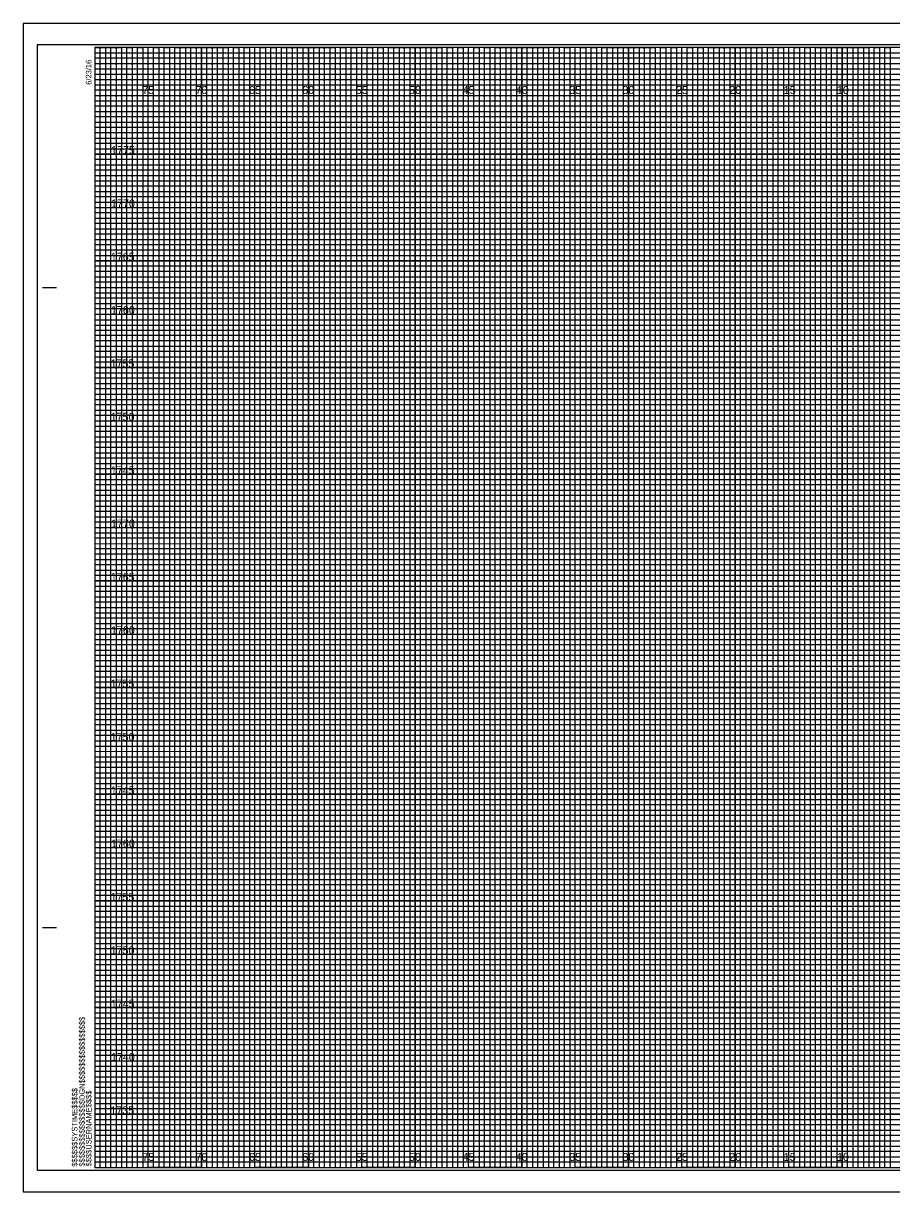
# Model space of a CAD drawing. Extents: x 224 to 392, y 1 to 440.
# Drawn here: x 223.6 to 304.9, y 1 to 110.5 of the extents above; entities that cross this region are included whole.
import ezdxf

# ---------------------------------------------------------------- set-up
doc = ezdxf.new("R2010")
doc.units = 0
for name, color, linetype in [('Prop Grid Mask', 7, 'Continuous'), ('Prop XS Elevation Labels', 7, 'Continuous'), ('Sheet Cross Section CELL', 7, 'Continuous'), ('Sheet Cross Section Grid Major CELL', 7, 'Continuous'), ('Sheet Cross Section Grid Middle CELL', 7, 'Continuous'), ('Sheet Cross Section Grid Minor 1 CELL', 7, 'Continuous'), ('Sheet Cross Section Grid Minor 2 CELL', 7, 'Continuous'), ('Sheet Cutting Line CELL', 7, 'Continuous'), ('Sheet DOT Grid CELL', 7, 'Continuous'), ('Sheet Plot Border Inside CELL', 7, 'Continuous'), ('Sheet Plot Border Outside CELL', 7, 'Continuous')]:
    doc.layers.add(name, color=color, linetype=linetype)

msp = doc.modelspace()

# ---------------------------------------------------------------- linework, layer by layer
at = {"layer": 'Sheet Cross Section CELL'}
for p, q in [((225.36, 85.71), (226.61, 85.71)), ((225.41, 85.71), (226.66, 85.71)), ((225.36, 25.71), (226.61, 25.71)), ((225.41, 25.71), (226.66, 25.71)), ((230.26, 3.21), (230.26, 3.21)), ((230.26, 3.21), (230.26, 3.21)), ((230.26, 3.21), (230.26, 3.21)), ((230.26, 3.21), (230.26, 3.21)), ((230.26, 3.21), (230.26, 3.21)), ((230.26, 3.21), (230.26, 3.21)), ((230.26, 3.21), (230.26, 3.21))]:
    msp.add_line(p, q, dxfattribs=at)
msp.add_lwpolyline([(390.26, 108.21), (230.26, 108.21), (230.26, 3.21), (390.26, 3.21)], close=True, dxfattribs=at)
at = {"layer": 'Sheet Cross Section Grid Major CELL'}
for p, q in [((235.26, 108.21), (230.26, 108.21)), ((235.26, 3.21), (235.26, 108.21)), ((245.26, 108.21), (240.26, 108.21)), ((240.26, 108.21), (240.26, 3.21)), ((245.26, 3.21), (245.26, 108.21)), ((255.26, 108.21), (250.26, 108.21)), ((250.26, 108.21), (250.26, 3.21)), ((255.26, 3.21), (255.26, 108.21)), ((265.26, 108.21), (260.26, 108.21)), ((260.26, 108.21), (260.26, 3.21)), ((265.26, 3.21), (265.26, 108.21)), ((275.26, 108.21), (270.26, 108.21)), ((270.26, 108.21), (270.26, 3.21)), ((275.26, 3.21), (275.26, 108.21)), ((285.26, 108.21), (280.26, 108.21)), ((280.26, 108.21), (280.26, 3.21)), ((285.26, 3.21), (285.26, 108.21)), ((295.26, 108.21), (290.26, 108.21)), ((290.26, 108.21), (290.26, 3.21)), ((295.26, 3.21), (295.26, 108.21)), ((305.26, 108.21), (300.26, 108.21)), ((300.26, 108.21), (300.26, 3.21)), ((240.26, 3.21), (235.26, 3.21)), ((250.26, 3.21), (245.26, 3.21)), ((260.26, 3.21), (255.26, 3.21)), ((270.26, 3.21), (265.26, 3.21)), ((280.26, 3.21), (275.26, 3.21)), ((290.26, 3.21), (285.26, 3.21)), ((300.26, 3.21), (295.26, 3.21))]:
    msp.add_line(p, q, dxfattribs=at)
for points in [[(230.26, 103.21), (390.26, 103.21), (390.26, 98.21), (230.26, 98.21)], [(230.26, 93.21), (390.26, 93.21), (390.26, 88.21), (230.26, 88.21)], [(230.26, 83.21), (390.26, 83.21), (390.26, 78.21), (230.26, 78.21)], [(230.26, 73.21), (390.26, 73.21), (390.26, 68.21), (230.26, 68.21)], [(230.26, 63.21), (390.26, 63.21), (390.26, 58.21), (230.26, 58.21)], [(230.26, 53.21), (390.26, 53.21), (390.26, 48.21), (230.26, 48.21)], [(230.26, 43.21), (390.26, 43.21), (390.26, 38.21), (230.26, 38.21)], [(230.26, 33.21), (390.26, 33.21), (390.26, 28.21), (230.26, 28.21)], [(230.26, 23.21), (390.26, 23.21), (390.26, 18.21), (230.26, 18.21)], [(230.26, 13.21), (390.26, 13.21), (390.26, 8.21), (230.26, 8.21)]]:
    msp.add_lwpolyline(points, dxfattribs=at)
at = {"layer": 'Sheet Cross Section Grid Middle CELL'}
for points in [[(230.26, 108.21), (232.76, 108.21), (232.76, 3.21), (237.76, 3.21), (237.76, 108.21), (242.76, 108.21), (242.76, 3.21), (247.76, 3.21), (247.76, 108.21), (252.76, 108.21), (252.76, 3.21), (257.76, 3.21), (257.76, 108.21), (262.76, 108.21), (262.76, 3.21), (267.76, 3.21), (267.76, 108.21), (272.76, 108.21), (272.76, 3.21), (277.76, 3.21), (277.76, 108.21), (282.76, 108.21), (282.76, 3.21), (287.76, 3.21), (287.76, 108.21), (292.76, 108.21), (292.76, 3.21), (297.76, 3.21), (297.76, 108.21), (302.76, 108.21), (302.76, 3.21), (307.76, 3.21)], [(230.26, 105.71), (367.76, 105.71)], [(230.26, 95.71), (390.26, 95.71), (390.26, 100.71), (230.26, 100.71)], [(230.26, 85.71), (390.26, 85.71), (390.26, 90.71), (230.26, 90.71)], [(230.26, 75.71), (390.26, 75.71), (390.26, 80.71), (230.26, 80.71)], [(230.26, 65.71), (390.26, 65.71), (390.26, 70.71), (230.26, 70.71)], [(230.26, 55.71), (390.26, 55.71), (390.26, 60.71), (230.26, 60.71)], [(230.26, 45.71), (390.26, 45.71), (390.26, 50.71), (230.26, 50.71)], [(230.26, 35.71), (390.26, 35.71), (390.26, 40.71), (230.26, 40.71)], [(230.26, 25.71), (390.26, 25.71), (390.26, 30.71), (230.26, 30.71)], [(230.26, 15.71), (390.26, 15.71), (390.26, 20.71), (230.26, 20.71)], [(230.26, 5.71), (390.26, 5.71), (390.26, 10.71), (230.26, 10.71)]]:
    msp.add_lwpolyline(points, dxfattribs=at)
at = {"layer": 'Sheet Cross Section Grid Minor 1 CELL'}
for p, q in [((230.26, 107.71), (360.26, 107.71)), ((360.26, 107.2), (230.26, 107.2)), ((230.26, 107.2), (230.26, 106.71)), ((230.26, 106.71), (360.26, 106.71)), ((360.26, 106.16), (230.26, 106.16)), ((230.26, 106.16), (230.26, 105.21)), ((230.26, 105.21), (390.26, 105.21))]:
    msp.add_line(p, q, dxfattribs=at)
for points in [[(230.26, 104.71), (365.26, 104.71), (390.26, 104.71), (390.26, 104.21), (230.26, 104.21)], [(230.26, 103.71), (390.26, 103.71), (390.26, 102.71), (230.26, 102.71)], [(230.26, 102.21), (390.26, 102.21), (390.26, 101.71), (230.26, 101.7)], [(230.26, 101.21), (390.26, 101.21), (390.26, 100.21), (230.26, 100.21)], [(230.26, 99.71), (390.26, 99.71), (390.26, 99.21), (230.26, 99.21)], [(230.26, 98.71), (390.26, 98.71), (390.26, 97.71), (230.26, 97.71)], [(230.26, 97.21), (390.26, 97.21), (390.26, 96.71), (230.26, 96.71)], [(230.26, 96.21), (390.26, 96.21), (390.26, 95.21), (230.26, 95.21)], [(230.26, 94.71), (390.26, 94.71), (390.26, 94.21), (230.26, 94.21)], [(230.26, 93.71), (390.26, 93.71), (390.26, 92.71), (230.26, 92.71)], [(230.26, 92.21), (390.26, 92.21), (390.26, 91.71), (230.26, 91.71)], [(230.26, 91.21), (390.26, 91.21), (390.26, 90.19), (390.26, 89.71), (390.26, 89.21), (230.26, 89.21)], [(230.26, 90.21), (390.26, 90.21), (390.26, 89.71), (230.26, 89.71)], [(230.26, 88.71), (390.26, 88.71), (390.26, 87.71), (230.26, 87.73)], [(230.26, 87.73), (390.26, 87.71), (390.26, 87.21), (230.26, 87.21)], [(230.26, 86.71), (390.26, 86.71), (390.26, 86.21), (230.26, 86.21)], [(230.26, 85.21), (390.26, 85.21), (390.26, 84.71), (230.26, 84.71)], [(230.26, 84.21), (390.26, 84.21), (390.26, 83.71), (230.26, 83.71)], [(230.23, 82.66), (390.26, 82.66), (390.26, 82.15), (230.23, 82.15)], [(230.26, 81.71), (390.26, 81.71), (390.26, 81.21), (230.26, 81.21)], [(230.26, 80.21), (390.26, 80.21), (390.26, 79.71), (230.26, 79.71)], [(230.26, 79.21), (390.26, 79.21), (390.26, 78.71), (230.26, 78.71)], [(230.26, 77.71), (390.26, 77.71), (390.26, 77.21), (230.26, 77.21)], [(230.26, 76.71), (390.26, 76.71), (390.26, 76.21), (230.26, 76.21)], [(230.26, 75.21), (390.26, 75.21), (390.26, 74.71), (230.26, 74.71)], [(230.26, 74.21), (390.26, 74.21), (390.26, 73.71), (230.26, 73.71)], [(230.26, 72.71), (390.26, 72.71), (390.26, 72.2), (230.26, 72.21)], [(230.26, 71.71), (390.26, 71.71), (390.26, 71.21), (230.26, 71.21)], [(230.26, 70.21), (390.26, 70.21), (390.26, 69.71), (230.26, 69.71)], [(230.26, 69.21), (390.26, 69.21), (390.26, 68.71), (230.26, 68.71)], [(230.26, 67.71), (390.26, 67.71), (390.26, 67.21), (230.26, 67.21)], [(230.26, 66.71), (390.26, 66.71), (390.26, 66.21), (230.26, 66.21)], [(230.26, 65.21), (390.26, 65.21), (390.26, 64.71), (230.26, 64.71)], [(230.26, 64.21), (390.26, 64.21), (390.26, 63.71), (230.26, 63.71)], [(230.26, 62.71), (390.26, 62.71), (390.26, 62.21), (230.26, 62.21)], [(230.26, 61.71), (390.3, 61.67), (390.26, 61.21), (230.26, 61.21)], [(230.26, 60.21), (390.26, 60.21), (390.26, 59.71), (230.26, 59.71)], [(230.26, 59.21), (390.26, 59.21), (390.26, 58.71), (230.26, 58.71)], [(230.26, 57.71), (390.26, 57.71), (390.26, 57.21), (230.26, 57.21)], [(230.26, 56.71), (390.26, 56.71), (390.26, 56.21), (230.26, 56.21)], [(230.26, 55.21), (390.26, 55.21), (390.26, 54.71), (230.26, 54.71)], [(230.26, 54.21), (390.26, 54.21), (390.26, 53.71), (230.26, 53.71)], [(230.26, 52.71), (390.26, 52.71), (390.26, 52.21), (230.26, 52.21)], [(230.26, 51.71), (390.26, 51.71), (390.26, 51.21), (230.26, 51.21)], [(230.26, 50.21), (390.26, 50.21), (390.26, 49.71), (230.26, 49.71)], [(230.26, 49.21), (390.26, 49.21), (390.26, 48.71), (230.26, 48.71)], [(230.26, 47.71), (390.26, 47.71), (390.26, 47.21), (230.26, 47.21)], [(230.26, 46.71), (390.26, 46.71), (390.26, 46.21), (230.26, 46.21)], [(230.26, 45.21), (390.26, 45.21), (390.26, 44.71), (230.26, 44.71)], [(230.26, 44.21), (390.26, 44.21), (390.26, 43.71), (230.26, 43.71)], [(230.26, 42.71), (390.26, 42.71), (390.26, 42.2), (230.26, 42.21)], [(230.26, 41.71), (390.26, 41.71), (390.26, 41.21), (230.26, 41.21)], [(230.26, 40.21), (390.26, 40.21), (390.26, 39.71), (230.26, 39.71)], [(230.26, 39.21), (390.26, 39.21), (390.26, 38.71), (230.26, 38.71)], [(230.26, 37.71), (390.26, 37.71), (390.26, 37.21), (230.26, 37.21)], [(230.26, 36.71), (390.26, 36.71), (390.26, 36.21), (230.26, 36.21)], [(230.26, 35.21), (390.26, 35.21), (390.26, 34.71), (230.26, 34.71)], [(230.26, 34.21), (390.26, 34.21), (390.26, 33.71), (230.26, 33.71)], [(230.26, 32.71), (390.26, 32.71), (390.26, 32.21), (230.26, 32.21)], [(230.26, 31.71), (390.3, 31.67), (390.26, 31.21), (230.26, 31.21)], [(230.26, 30.21), (390.26, 30.21), (390.26, 29.71), (230.26, 29.71)], [(230.26, 29.21), (390.26, 29.21), (390.26, 28.71), (230.26, 28.71)], [(230.26, 27.71), (390.26, 27.71), (390.26, 27.21), (230.26, 27.21)], [(230.26, 26.71), (390.26, 26.71), (390.26, 26.21), (230.26, 26.21)], [(230.26, 25.21), (390.26, 25.21), (390.26, 24.71), (230.26, 24.71)], [(230.26, 24.21), (390.26, 24.21), (390.26, 23.71), (230.26, 23.71)], [(230.26, 22.71), (390.26, 22.71), (390.26, 22.21), (230.26, 22.21)], [(230.26, 21.71), (390.26, 21.71), (390.26, 21.21), (230.26, 21.21)], [(230.26, 20.21), (390.26, 20.21), (390.26, 19.71), (230.26, 19.71)], [(230.26, 19.21), (390.26, 19.21), (390.26, 18.71), (230.26, 18.71)], [(230.26, 17.71), (390.26, 17.71), (390.26, 17.21), (230.26, 17.21)], [(230.26, 16.71), (390.26, 16.71), (390.26, 16.21), (230.26, 16.21)], [(230.26, 15.21), (390.26, 15.21), (390.26, 14.71), (230.26, 14.71)], [(230.26, 14.21), (390.26, 14.21), (390.26, 13.71), (230.26, 13.71)], [(230.26, 12.71), (390.26, 12.71), (390.26, 12.21), (230.26, 12.21)], [(230.26, 11.71), (390.26, 11.71), (390.26, 11.21), (230.26, 11.21)], [(230.26, 10.21), (390.26, 10.21), (390.26, 9.71), (230.26, 9.71)], [(230.26, 9.21), (390.26, 9.21), (390.26, 8.71), (230.26, 8.71)], [(230.26, 7.71), (390.26, 7.71), (390.26, 7.21), (230.26, 7.21)], [(230.26, 6.71), (390.26, 6.71), (390.26, 6.21), (230.26, 6.21)], [(230.26, 5.21), (390.26, 5.21), (390.26, 4.71), (230.26, 4.71)], [(230.26, 4.21), (390.26, 4.21), (390.26, 3.71), (230.26, 3.71)]]:
    msp.add_lwpolyline(points, dxfattribs=at)
at = {"layer": 'Sheet Cross Section Grid Minor 2 CELL'}
for points in [[(230.26, 3.21), (230.76, 3.21), (230.76, 108.21), (231.26, 108.21), (231.26, 3.21)], [(231.26, 3.21), (231.76, 3.21), (231.76, 108.21), (232.26, 108.21), (232.26, 3.21)], [(232.76, 3.21), (233.26, 3.21), (233.26, 108.21), (233.76, 108.21), (233.76, 3.21)], [(233.76, 3.21), (234.26, 3.21), (234.26, 108.21), (234.76, 108.21), (234.76, 3.21)], [(235.26, 3.21), (235.76, 3.21), (235.76, 108.21), (236.26, 108.21), (236.26, 3.21)], [(236.26, 3.21), (236.76, 3.21), (236.76, 108.21), (237.26, 108.21), (237.26, 3.21)], [(237.76, 3.21), (238.26, 3.21), (238.26, 108.21), (238.76, 108.21), (238.76, 3.21)], [(238.76, 3.21), (239.26, 3.21), (239.26, 108.21), (239.76, 108.21), (239.76, 3.21)], [(240.26, 3.21), (240.76, 3.21), (240.76, 108.21), (241.26, 108.21), (241.26, 3.21)], [(241.26, 3.21), (241.76, 3.21), (241.76, 108.21), (242.26, 108.21), (242.26, 3.21)], [(242.76, 3.21), (243.26, 3.21), (243.26, 108.21), (243.76, 108.21), (243.76, 3.21)], [(243.76, 3.21), (244.26, 3.21), (244.26, 108.21), (244.76, 108.21), (244.76, 3.21)], [(245.26, 3.21), (245.76, 3.21), (245.76, 108.21), (246.26, 108.21), (246.26, 3.21)], [(246.26, 3.21), (246.76, 3.21), (246.76, 108.21), (247.26, 108.21), (247.26, 3.21)], [(247.76, 3.21), (248.26, 3.21), (248.26, 108.21), (248.76, 108.21), (248.76, 3.21)], [(248.76, 3.21), (249.26, 3.21), (249.26, 108.21), (249.76, 108.21), (249.76, 3.21)], [(250.26, 3.21), (250.76, 3.21), (250.76, 108.21), (251.26, 108.21), (251.26, 3.21)], [(251.26, 3.21), (251.76, 3.21), (251.76, 108.21), (252.26, 108.21), (252.26, 3.21)], [(252.76, 3.21), (253.26, 3.21), (253.26, 108.21), (253.76, 108.21), (253.76, 3.21)], [(253.76, 3.21), (254.26, 3.21), (254.26, 108.21), (254.76, 108.21), (254.76, 3.21)], [(255.26, 3.21), (255.76, 3.21), (255.76, 108.21), (256.26, 108.21), (256.26, 3.21)], [(256.26, 3.21), (256.76, 3.21), (256.76, 108.21), (257.26, 108.21), (257.26, 3.21)], [(257.76, 3.21), (258.26, 3.21), (258.26, 108.21), (258.76, 108.21), (258.76, 3.21)], [(258.76, 3.21), (259.26, 3.21), (259.26, 108.21), (259.76, 108.21), (259.76, 3.21)], [(260.26, 3.21), (260.76, 3.21), (260.76, 108.21), (261.26, 108.21), (261.26, 3.21)], [(261.26, 3.21), (261.76, 3.21), (261.76, 108.21), (262.26, 108.21), (262.26, 3.21)], [(262.76, 3.21), (263.26, 3.21), (263.26, 108.21), (263.76, 108.21), (263.76, 3.21)], [(263.76, 3.21), (264.26, 3.21), (264.26, 108.21), (264.76, 108.21), (264.76, 3.21)], [(265.26, 3.21), (265.76, 3.21), (265.76, 108.21), (266.26, 108.21), (266.26, 3.21)], [(266.26, 3.21), (266.76, 3.21), (266.76, 108.21), (267.26, 108.21), (267.26, 3.21)], [(267.76, 3.21), (268.26, 3.21), (268.26, 108.21), (268.76, 108.21), (268.76, 3.21)], [(268.76, 3.21), (269.26, 3.21), (269.26, 108.21), (269.76, 108.21), (269.76, 3.21)], [(270.26, 3.21), (270.76, 3.21), (270.76, 108.21), (271.26, 108.21), (271.26, 3.21)], [(271.26, 3.21), (271.76, 3.21), (271.76, 108.21), (272.26, 108.21), (272.26, 3.21)], [(272.76, 3.21), (273.26, 3.21), (273.26, 108.21), (273.76, 108.21), (273.76, 3.21)], [(273.76, 3.21), (274.26, 3.21), (274.26, 108.21), (274.76, 108.21), (274.76, 3.21)], [(275.26, 3.21), (275.76, 3.21), (275.76, 108.21), (276.26, 108.21), (276.26, 3.21)], [(276.26, 3.21), (276.76, 3.21), (276.76, 108.21), (277.26, 108.21), (277.26, 3.21)], [(277.76, 3.21), (278.26, 3.21), (278.26, 108.21), (278.76, 108.21), (278.76, 3.21)], [(278.76, 3.21), (279.26, 3.21), (279.26, 108.21), (279.76, 108.21), (279.76, 3.21)], [(280.26, 3.21), (280.76, 3.21), (280.76, 108.21), (281.26, 108.21), (281.26, 3.21)], [(281.26, 3.21), (281.76, 3.21), (281.76, 108.21), (282.26, 108.21), (282.26, 3.21)], [(282.76, 3.21), (283.26, 3.21), (283.26, 108.21), (283.76, 108.21), (283.76, 3.21)], [(283.76, 3.21), (284.26, 3.21), (284.26, 108.21), (284.76, 108.21), (284.76, 3.21)], [(285.26, 3.21), (285.76, 3.21), (285.76, 108.21), (286.26, 108.21), (286.26, 3.21)], [(286.26, 3.21), (286.76, 3.21), (286.76, 108.21), (287.26, 108.21), (287.26, 3.21)], [(287.76, 3.21), (288.26, 3.21), (288.26, 108.21), (288.76, 108.21), (288.76, 3.21)], [(288.76, 3.21), (289.26, 3.21), (289.26, 108.21), (289.76, 108.21), (289.76, 3.21)], [(290.26, 3.21), (290.76, 3.21), (290.76, 108.21), (291.26, 108.21), (291.26, 3.21)], [(291.26, 3.21), (291.76, 3.21), (291.76, 108.21), (292.26, 108.21), (292.26, 3.21)], [(292.76, 3.21), (293.26, 3.21), (293.26, 108.21), (293.76, 108.21), (293.76, 3.21)], [(293.76, 3.21), (294.26, 3.21), (294.26, 108.21), (294.76, 108.21), (294.76, 3.21)], [(295.26, 3.21), (295.76, 3.21), (295.76, 108.21), (296.26, 108.21), (296.26, 3.21)], [(296.26, 3.21), (296.76, 3.21), (296.76, 108.21), (297.26, 108.21), (297.26, 3.21)], [(297.76, 3.21), (298.26, 3.21), (298.26, 108.21), (298.76, 108.21), (298.76, 3.21)], [(298.76, 3.21), (299.26, 3.21), (299.26, 108.21), (299.76, 108.21), (299.76, 3.21)], [(300.26, 3.21), (300.76, 3.21), (300.76, 108.21), (301.26, 108.21), (301.26, 3.21)], [(301.26, 3.21), (301.76, 3.21), (301.76, 108.21), (302.26, 108.21), (302.26, 3.21)], [(302.76, 3.21), (303.26, 3.21), (303.26, 108.21), (303.76, 108.21), (303.76, 3.21)], [(303.76, 3.21), (304.26, 3.21), (304.26, 108.21), (304.76, 108.21), (304.76, 3.21)]]:
    msp.add_lwpolyline(points, dxfattribs=at)
at = {"layer": 'Sheet Cutting Line CELL'}
for p, q in [((391.91, 110.46), (223.56, 110.46)), ((223.56, 110.46), (223.56, 0.96)), ((223.56, 0.96), (391.91, 0.96))]:
    msp.add_line(p, q, dxfattribs=at)
at = {"layer": 'Sheet DOT Grid CELL'}
for p, q in [((235.26, 3.21), (235.26, 108.21)), ((240.26, 3.21), (240.26, 108.21)), ((245.26, 3.21), (245.26, 108.21)), ((250.26, 3.21), (250.26, 108.21)), ((255.26, 3.21), (255.26, 108.21)), ((260.26, 3.21), (260.26, 108.21)), ((265.26, 3.21), (265.26, 108.21)), ((270.26, 3.21), (270.26, 108.21)), ((275.26, 3.21), (275.26, 108.21)), ((280.26, 3.21), (280.26, 108.21)), ((285.26, 3.21), (285.26, 108.21)), ((290.26, 3.21), (290.26, 108.21)), ((295.26, 3.21), (295.26, 108.21)), ((300.26, 3.21), (300.26, 108.21)), ((230.26, 103.21), (390.26, 103.21)), ((230.26, 98.21), (390.26, 98.21)), ((230.26, 93.21), (390.26, 93.21)), ((230.26, 88.21), (390.26, 88.21)), ((230.26, 83.21), (390.26, 83.21)), ((230.26, 78.21), (390.26, 78.21)), ((230.26, 73.21), (390.26, 73.21)), ((230.26, 68.21), (390.26, 68.21)), ((230.26, 63.21), (390.26, 63.21)), ((230.26, 58.21), (390.26, 58.21)), ((230.26, 53.21), (390.26, 53.21)), ((230.26, 48.21), (390.26, 48.21)), ((230.26, 43.21), (390.26, 43.21)), ((230.26, 38.21), (390.26, 38.21)), ((230.26, 33.21), (390.26, 33.21)), ((230.26, 28.21), (390.26, 28.21)), ((230.26, 23.21), (390.26, 23.21)), ((230.26, 18.21), (390.26, 18.21)), ((230.26, 13.21), (390.26, 13.21)), ((230.26, 8.21), (390.26, 8.21))]:
    msp.add_line(p, q, dxfattribs=at)
at = {"layer": 'Sheet Plot Border Inside CELL'}
msp.add_lwpolyline([(224.86, 2.96), (391.46, 2.96), (391.46, 108.46), (224.86, 108.46)], close=True, dxfattribs=at)
at = {"layer": 'Sheet Plot Border Outside CELL'}
msp.add_lwpolyline([(223.56, 0.96), (391.91, 0.96), (391.91, 110.46), (223.56, 110.46)], close=True, dxfattribs=at)

# ---------------------------------------------------------------- texts
at = {"layer": 'Prop Grid Mask'}
for s, p in [('75', (234.71, 103.84)), ('70', (239.69, 103.84)), ('65', (244.71, 103.84)), ('60', (249.69, 103.84)), ('55', (254.71, 103.84)), ('50', (259.69, 103.84)), ('45', (264.71, 103.84)), ('40', (269.69, 103.84)), ('35', (274.71, 103.84)), ('30', (279.69, 103.84)), ('25', (284.71, 103.84)), ('20', (289.69, 103.84)), ('15', (294.8, 103.84)), ('10', (299.78, 103.84)), ('75', (234.71, 3.84)), ('70', (239.69, 3.84)), ('65', (244.71, 3.84)), ('60', (249.69, 3.84)), ('55', (254.71, 3.84)), ('50', (259.69, 3.84)), ('45', (264.71, 3.84)), ('40', (269.69, 3.84)), ('35', (274.71, 3.84)), ('30', (279.69, 3.84)), ('25', (284.71, 3.84)), ('20', (289.69, 3.84)), ('15', (294.8, 3.84)), ('10', (299.78, 3.84))]:
    msp.add_text(s, height=0.75, dxfattribs=at).set_placement(p)
at = {"layer": 'Prop XS Elevation Labels'}
for s, p in [('1775', (231.78, 98.21)), ('1770', (231.78, 93.21)), ('1765', (231.76, 88.21)), ('1760', (231.77, 83.21)), ('1755', (231.73, 78.21)), ('1750', (231.74, 73.21)), ('1745', (231.76, 68.21)), ('1770', (231.78, 63.21)), ('1765', (231.76, 58.21)), ('1760', (231.77, 53.21)), ('1755', (231.73, 48.21)), ('1750', (231.74, 43.21)), ('1745', (231.76, 38.21)), ('1760', (231.77, 33.21)), ('1755', (231.73, 28.21)), ('1750', (231.74, 23.21)), ('1745', (231.76, 18.21)), ('1740', (231.77, 13.21)), ('1735', (231.72, 8.21))]:
    msp.add_text(s, height=0.75, dxfattribs=at).set_placement(p)
at = {"layer": 'Sheet Cross Section CELL'}
for s, p in [('6/23/16', (229.94, 104.71)), ('$$$$$$$$$$$$$$$$DGN$$$$$$$$$$$$$$$$', (229.32, 3.3)), ('$$$$$$SYSTIME$$$$$', (228.63, 3.3)), ('$$$$USERNAME$$$$', (229.95, 3.33))]:
    msp.add_text(s, height=0.525, rotation=90, dxfattribs=at).set_placement(p)

doc.saveas('drawing.dxf')
